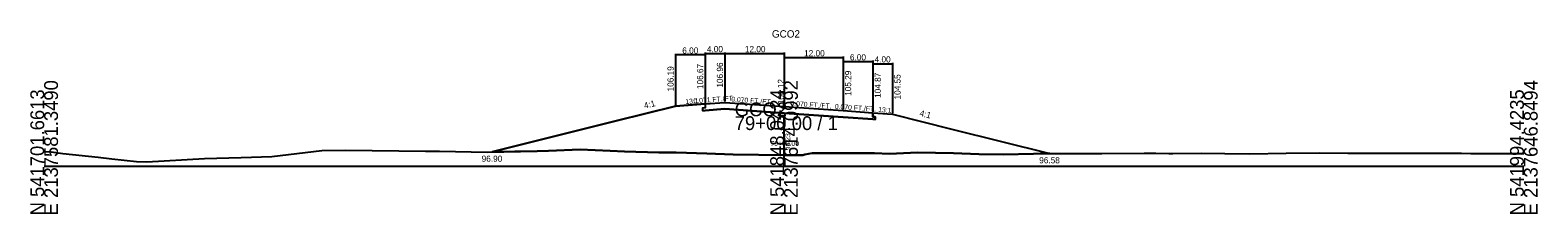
# Model space of a CAD drawing. Extents: x -14327 to 8886, y -10 to 39048.
# Drawn here: x 2997.2 to 3302.8, y 17990.3 to 18027.6 of the extents above; entities that cross this region are included whole.
import ezdxf

# ---------------------------------------------------------------- set-up
doc = ezdxf.new("R2010")
doc.units = 0
for name, color, linetype in [('Level 5', 7, 'Continuous'), ('Level 53', 7, 'Continuous'), ('Level 54', 7, 'Continuous'), ('Level 55', 7, 'Continuous'), ('Level 7', 7, 'Continuous'), ('RD_GPK_XS_Cell', 7, 'Continuous'), ('RD_XS_EwShp', 7, 'Continuous'), ('RD_XS_ExGround', 7, 'Continuous'), ('RD_XS_Pave', 7, 'Continuous'), ('RD_XS_TX_Baseline', 7, 'Continuous'), ('RD_XS_TX_Elev_EX', 7, 'Continuous'), ('RD_XS_TX_Elev_PR', 7, 'Continuous'), ('RD_XS_TX_Station', 7, 'Continuous')]:
    doc.layers.add(name, color=color, linetype=linetype)

msp = doc.modelspace()

# ---------------------------------------------------------------- linework, layer by layer
at = {"layer": 'Level 5'}
for p, q in [((3134, 18011.84), (3133.5, 18011.81)), ((3133.5, 18011.81), (3133.5, 18011.31)), ((3133.5, 18011.31), (3134, 18011.34)), ((3134, 18012.67), (3134, 18011.84)), ((3138, 18011.62), (3134, 18011.34)), ((3150, 18010.79), (3138, 18011.62)), ((3162, 18009.95), (3150, 18010.79)), ((3168, 18010.87), (3168, 18010.04)), ((3168, 18009.54), (3162, 18009.95)), ((3168, 18010.04), (3168.5, 18010)), ((3168.5, 18009.5), (3168, 18009.54)), ((3168.5, 18010), (3168.5, 18009.5))]:
    msp.add_line(p, q, dxfattribs=at)
at = {"layer": 'Level 54'}
for p, q in [((3134, 18023.11), (3134, 18012.87)), ((3138, 18023.11), (3138, 18013.16)), ((3150, 18023.11), (3150, 18012.32)), ((3128, 18022.82), (3128, 18012.39)), ((3134, 18022.62), (3128, 18022.62)), ((3134, 18022.91), (3138, 18022.91)), ((3134, 18022.82), (3134, 18012.87)), ((3138, 18022.91), (3150, 18022.91)), ((3150, 18022.27), (3150, 18012.32)), ((3150, 18022.07), (3162, 18022.07)), ((3162, 18022.27), (3162, 18011.49)), ((3162, 18021.44), (3162, 18011.49)), ((3162, 18021.24), (3168, 18021.24)), ((3168, 18021.44), (3168, 18011.07)), ((3168, 18021.02), (3168, 18011.07)), ((3168, 18020.82), (3172, 18020.82)), ((3172, 18021.02), (3172, 18010.75))]:
    msp.add_line(p, q, dxfattribs=at)
at = {"layer": 'Level 7'}
for p, q in [((3128, 18012.19), (3116, 18009.19)), ((3134, 18012.67), (3128, 18012.19)), ((3168, 18010.87), (3172, 18010.55)), ((3116, 18009.19), (3090.81, 18002.9)), ((3172, 18010.55), (3184, 18007.55)), ((3184, 18007.55), (3203.89, 18002.58))]:
    msp.add_line(p, q, dxfattribs=at)
at = {"layer": 'RD_GPK_XS_Cell'}
for p, q in [((3150, 18000), (3150, 18010.14)), ((3000, 18000), (3150, 18000)), ((3150, 18000), (3300, 18000))]:
    msp.add_line(p, q, dxfattribs=at)
at = {"layer": 'RD_XS_EwShp'}
msp.add_lwpolyline([(3172, 18010.55), (3184, 18007.55), (3203.89, 18002.58), (3201.98, 18002.58), (3200.59, 18002.54), (3194.43, 18002.38), (3189.52, 18002.47), (3184.39, 18002.67), (3177.06, 18002.75), (3171.39, 18002.54), (3168.37, 18002.64), (3167.87, 18002.64), (3155.69, 18002.63), (3154.24, 18002.36), (3153.79, 18002.25), (3151.84, 18002.23), (3150, 18002.23), (3139.66, 18002.37), (3134.32, 18002.55), (3128.12, 18002.75), (3125.63, 18002.81), (3124.94, 18002.76), (3124.63, 18002.77), (3117.67, 18002.95), (3114.73, 18003.09), (3108.68, 18003.38), (3102.27, 18003.1), (3099.96, 18003.04), (3090.81, 18002.9), (3116, 18009.19), (3128, 18012.19), (3134, 18012.67), (3134, 18011.84), (3133.5, 18011.81), (3133.5, 18011.31), (3134, 18011.34), (3138, 18011.62), (3150, 18010.79), (3162, 18009.95), (3168, 18009.54), (3168.5, 18009.5), (3168.5, 18010), (3168, 18010.04), (3168, 18010.87)], close=True, dxfattribs=at)
at = {"layer": 'RD_XS_ExGround'}
for p, q in [((3000, 18002.96), (3001.39, 18002.89)), ((3001.39, 18002.89), (3003.77, 18002.55)), ((3003.77, 18002.55), (3010.92, 18001.84)), ((3010.92, 18001.84), (3013.71, 18001.51)), ((3032.52, 18001.53), (3039.94, 18001.79)), ((3039.94, 18001.79), (3046.17, 18002)), ((3046.17, 18002), (3056.32, 18003.19)), ((3056.32, 18003.19), (3061.09, 18003.25)), ((3061.09, 18003.25), (3077.34, 18003.08)), ((3077.34, 18003.08), (3080.12, 18003.04)), ((3080.12, 18003.04), (3089.8, 18002.88)), ((3089.8, 18002.88), (3099.96, 18003.04)), ((3099.96, 18003.04), (3102.27, 18003.1)), ((3102.27, 18003.1), (3108.68, 18003.38)), ((3108.68, 18003.38), (3114.73, 18003.09)), ((3114.73, 18003.09), (3117.67, 18002.95)), ((3117.67, 18002.95), (3124.63, 18002.77)), ((3124.63, 18002.77), (3124.94, 18002.76)), ((3124.94, 18002.76), (3125.63, 18002.81)), ((3125.63, 18002.81), (3128.12, 18002.75)), ((3128.12, 18002.75), (3134.32, 18002.55)), ((3134.32, 18002.55), (3139.66, 18002.37)), ((3139.66, 18002.37), (3150, 18002.23)), ((3150, 18002.23), (3151.84, 18002.23)), ((3151.84, 18002.23), (3153.79, 18002.25)), ((3153.79, 18002.25), (3154.24, 18002.36)), ((3154.24, 18002.36), (3155.69, 18002.63)), ((3155.69, 18002.63), (3167.87, 18002.64)), ((3167.87, 18002.64), (3168.37, 18002.64)), ((3168.37, 18002.64), (3171.39, 18002.54)), ((3171.39, 18002.54), (3177.06, 18002.75)), ((3177.06, 18002.75), (3184.39, 18002.67)), ((3184.39, 18002.67), (3189.52, 18002.47)), ((3189.52, 18002.47), (3194.43, 18002.38)), ((3194.43, 18002.38), (3200.59, 18002.54)), ((3200.59, 18002.54), (3201.98, 18002.58)), ((3201.98, 18002.58), (3210.74, 18002.57)), ((3210.74, 18002.57), (3214.45, 18002.6)), ((3214.45, 18002.6), (3223.04, 18002.66)), ((3223.04, 18002.66), (3225.37, 18002.63)), ((3225.37, 18002.63), (3228.01, 18002.55)), ((3228.01, 18002.55), (3228.85, 18002.61)), ((3228.85, 18002.61), (3234.66, 18002.64)), ((3234.66, 18002.64), (3239.38, 18002.61)), ((3239.38, 18002.61), (3244.47, 18002.5)), ((3244.47, 18002.5), (3251.84, 18002.64)), ((3251.84, 18002.64), (3258.65, 18002.7)), ((3258.65, 18002.7), (3264.31, 18002.63)), ((3264.31, 18002.63), (3265.76, 18002.64)), ((3265.76, 18002.64), (3275, 18002.63)), ((3275, 18002.63), (3284.75, 18002.66)), ((3284.75, 18002.66), (3287.35, 18002.63)), ((3287.35, 18002.63), (3289.24, 18002.57)), ((3289.24, 18002.57), (3300, 18002.56)), ((3013.71, 18001.51), (3018.75, 18000.93)), ((3018.75, 18000.93), (3020.82, 18000.89)), ((3020.82, 18000.89), (3032.52, 18001.53))]:
    msp.add_line(p, q, dxfattribs=at)
at = {"layer": 'RD_XS_Pave'}
for p, q in [((3134, 18012.67), (3138, 18012.96)), ((3138, 18012.96), (3150, 18012.12)), ((3150, 18012.12), (3162, 18011.29)), ((3162, 18011.29), (3168, 18010.87))]:
    msp.add_line(p, q, dxfattribs=at)

# ---------------------------------------------------------------- texts
at = {"layer": 'Level 53'}
for s, rotation, p in [('106.19', 90, (3127.62, 18015.19)), ('106.67', 90, (3133.62, 18015.67)), ('106.96', 90, (3137.63, 18015.96)), ('105.29', 90, (3163.62, 18014.29)), ('104.87', 90, (3169.63, 18013.87)), ('104.55', 90, (3173.63, 18013.55)), ('4:1', 14.0362, (3121.76, 18011.66)), ('4:1', 345.9638, (3177.39, 18010.23))]:
    msp.add_text(s, height=1.25, rotation=rotation, dxfattribs=at).set_placement(p)
for s, p in [('96.90', (3088.7, 18000.9)), ('96.58', (3201.74, 18000.58))]:
    msp.add_text(s, height=1.25, dxfattribs=at).set_placement(p)
at = {"layer": 'Level 54'}
for s, p in [('6.00', (3129.37, 18022.87)), ('4.00', (3134.37, 18023.16)), ('12.00', (3142.07, 18023.16)), ('12.00', (3154.07, 18022.32)), ('6.00', (3163.37, 18021.49)), ('4.00', (3168.37, 18021.07))]:
    msp.add_text(s, height=1.25, dxfattribs=at).set_placement(p)
at = {"layer": 'Level 55'}
for s, rotation, p in [('0.071 FT./FT.', 4.058, (3131.68, 18012.76)), ('0.070 FT./FT.', 356.0172, (3139.28, 18013.12)), ('13:1', 4.5739, (3130.03, 18012.61)), ('0.070 FT./FT.', 356.0172, (3151.28, 18012.28)), ('0.070 FT./FT.', 356.0172, (3160.28, 18011.66)), ('13:1', 355.4261, (3169.07, 18011.03))]:
    msp.add_text(s, height=1, rotation=rotation, dxfattribs=at).set_placement(p)
at = {"layer": 'RD_GPK_XS_Cell'}
for s, p in [('E 2137581.3490', (3002.8, 17990)), ('E 2137614.0992', (3152.8, 17990)), ('E 2137646.8494', (3302.8, 17990)), ('N 541701.6613', (3000, 17990)), ('N 541848.0424', (3150, 17990)), ('N 541994.4235', (3300, 17990))]:
    msp.add_text(s, height=2.8, rotation=90, dxfattribs=at).set_placement(p)
for s, p in [('GCO2', (3140, 18010.14)), ('79+00.00 / 1', (3140, 18007.34))]:
    msp.add_text(s, height=2.8, dxfattribs=at).set_placement(p)
at = {"layer": 'RD_XS_TX_Baseline'}
msp.add_text('GCO2', height=1.5, dxfattribs=at).set_placement((3147.55, 18026.12))
at = {"layer": 'RD_XS_TX_Elev_EX'}
msp.add_text('96.23', height=1, rotation=90, dxfattribs=at).set_placement((3151.25, 18003.23))
at = {"layer": 'RD_XS_TX_Elev_PR'}
msp.add_text(' 106.12', height=1.25, rotation=90, dxfattribs=at).set_placement((3150, 18012.12))
at = {"layer": 'RD_XS_TX_Station'}
msp.add_text('79+00.00', height=1, dxfattribs=at).set_placement((3147.25, 18004.12))

doc.saveas('drawing.dxf')
